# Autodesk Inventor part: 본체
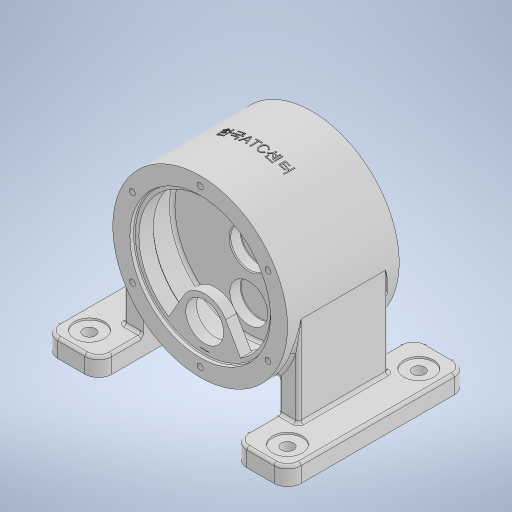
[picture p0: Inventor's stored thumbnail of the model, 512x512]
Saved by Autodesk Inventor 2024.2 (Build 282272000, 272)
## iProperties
Created: 2025-12
Part Number: 본체
Material: 일반
Document SubType Name: Modeling
Designer: home
Density: 1 g/cm^3
Appearance: 기본값
Author: home
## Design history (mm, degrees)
sketch "스케치1"
  geometry: L1 (135, -100)-(75, -100); L2 (75, -100)-(75, 100); L3 (75, 100)-(135, 100); L4 (135, 100)-(135, -100); L5 (-75, -100)-(-135, -100); L6 (-135, -100)-(-135, 100); L7 (-135, 100)-(-75, 100); L8 (-75, 100)-(-75, -100); 2 further points
  constraints: 16 end point, 4 parallel, 2 horizontal, 2 perpendicular, 1 midpoint
  dimensions: "d0" = 60 distance between parallel lines of L2 L4; "d1" = 60 distance between parallel lines of L6 L8; "d2" = 135 distance from line of point (0, 0) L4; "d3" = 135 distance from line of point (0, 0) L6; "d4" = 100 vertical distance of point (-105, -100) point (0, 0); "d5" = 100 distance from line of L7 point (0, 0); "d6" = 100 distance from line of point (0, 0) L1; "d7" = 100 distance from line of point (0, 0) L3
extrude "돌출1" new body sketch "스케치1" distance "d8" = 20; taper "d9" = 0 deg
sketch "스케치2"
  geometry: C1 r 97 at (0, 120); 1 further point
  constraints: 1 centre point, 1 vertical alignment
  dimensions: "d11" = 194 diameter of C1
extrude "돌출2" join sketch "스케치2" stored distance "d12" = 124; taper "d13" = 0 deg
sketch "스케치3"
  geometry: L1 (-135, 20)-(-75, 20) reference; L2 (75, 20)-(135, 20) reference; L3 (97, 120)-(97, 20); L4 (-97, 120)-(-97, 20); L5 (-75, 58.486)-(-75, 20); L6 (75, 20)-(75, 58.486); A1 r 97 centre (0, 120) between (97, 120) and (-97, 120) reference; 1 further point
  constraints: 8 end point, 4 point on circle, 2 perpendicular, 2 point on line, 2 tangent, 2 vertical
extrude "돌출3" join sketch "스케치3" stored distance "d14" = 100; taper "d15" = 0 deg
extrude "돌출4" join sketch "스케치3" stored distance "d16" = 100; taper "d17" = 0 deg
sketch "스케치4"
  geometry: L1 (120, 142.24)-(120, -159.656); L2 (0, 100)-(0, -100) reference; L3 (217, 62)-(23, 62) reference; L4 (23, -62)-(217, -62) reference; L5 (141, 8)-(141, -4); L6 (141, -4)-(120, -4); L7 (120, -4)-(120, 7.39); L8 (120, -4)-(139, -4); L9 (120, -13.476)-(120, -4); L10 (120, 62)-(198, 62); L11 (198, 62)-(198, 57); L12 (198, 57)-(120, 57); L13 (120, 57)-(120, 62); L14 (120, -62)-(198, -62); L15 (198, -62)-(198, -57); L16 (198, -57)-(120, -57); L17 (120, -57)-(120, -62); L18 (120, -57)-(193, -57); L19 (193, -57)-(193, -40); L20 (193, -40)-(120, -40); L21 (120, -40)-(120, -57); L22 (120, -40)-(205, -40); L23 (205, -40)-(205, -8); L24 (205, -8)-(120, -8); L25 (120, -8)-(120, -40); L26 (120, -4)-(139, -4); L27 (139, -4)-(139, -8); L28 (139, -8)-(120, -8); L29 (120, -8)-(120, -4); L30 (256.411, 0)-(-60.055, 0); L31 (205, 40)-(205, 8); L32 (205, 8)-(120, 8); L33 (120, 40)-(205, 40); L34 (141, 57)-(193, 57); L35 (193, 57)-(193, 40); L36 (193, 40)-(141, 40); L37 (141, 40)-(141, 57); L38 (67.5, 77.208)-(67.5, -163.094); L39 (120, 50)-(58.486, 50) reference; L40 (67.5, 57)-(88.5, 57); L41 (88.5, 57)-(88.5, 50); L42 (88.5, 50)-(67.5, 50); L43 (67.5, 50)-(67.5, 57); L44 (67.5, 50)-(89.75, 50); L45 (89.75, 50)-(89.75, 48.05); L46 (89.75, 48.05)-(67.5, 48.05); L47 (67.5, 48.05)-(67.5, 50); L48 (67.5, 48.05)-(88.5, 48.05); L49 (88.5, 48.05)-(88.5, 36.05); L50 (88.5, 36.05)-(67.5, 36.05); L51 (67.5, 36.05)-(67.5, 48.05); L52 (120, -4)-(67.5, -4); L53 (120, -8)-(67.5, -8); L54 (120, 8)-(67.5, 8); L55 (86.5, -4)-(86.5, -8); L56 (67.5, -4)-(88.5, -4); L57 (88.5, -4)-(88.5, 8); L58 (88.5, 8)-(67.5, 8); L59 (67.5, 8)-(67.5, -4); 23 further points
  constraints: 110 end point, 21 parallel, 13 perpendicular, 13 point on line, 12 horizontal, 4 symmetric about line, 2 midpoint, 2 vertical
  dimensions: "d18" = 120 distance between parallel lines of L2 L1; "d19" = 66 distance between parallel lines of L6 L3; "d20" = 42 diameter of L5 L1; "d22" = 5 distance of L10.end L11.end; "d23" = 156 diameter of L11 L1; "d24" = 5 distance of L14.end L15.end; "d25" = 156 diameter of L15 L1; "d26" = 22 distance between parallel lines of L4 L20; "d27" = 146 diameter of L19 L1; "d28" = 32 distance of L22.end L23.end; "d29" = 170 diameter of L23 L1; "d30" = 38 diameter of L27 L1; "d32" = 22 distance between parallel lines of L33 L3; "d35" = 146 diameter of L35 L1; "d37" = 42 diameter of L41 L38; "d38" = 44.5 diameter of L45 L38; "d39" = 1.95 distance between parallel lines of L46 L39; "d40" = 12 distance between parallel lines of L50 L46; "d41" = 42 diameter of L49 L38; "d42" = 19 distance of L6.end L8.end; "d43" = 42 diameter of L57 L38; "d44" = 38 diameter of L55 L38; "d47" = 52.5 distance between parallel lines of L38 L1
revolve "회전1" stored, may be unused: angle "d31" = 360 deg
revolve "회전2" stored, may be unused: angle "d45" = 90 deg
revolve "회전3" stored, may be unused: angle "d46" = 90 deg
fillet "모깎기1" dims "d48" = 15
sketch "스케치5"
  geometry: L1 (-135, 85)-(-135, -85) reference; L2 (-120, -100)-(-90, -100) reference; L3 (-75, -85)-(-75, -50) reference; L4 (-75, -50)-(-97, -50) reference; L5 (-97, -50)-(-97, 50) reference; L6 (-97, 50)-(-75, 50) reference; L7 (-75, 50)-(-75, 85) reference; L8 (-90, 100)-(-120, 100) reference; L9 (90, -100)-(120, -100) reference; L10 (135, -85)-(135, 85) reference; L11 (120, 100)-(90, 100) reference; L12 (75, 85)-(75, 50) reference; L13 (75, 50)-(97, 50) reference; L14 (97, 50)-(97, -50) reference; L15 (97, -50)-(75, -50) reference; L16 (75, -50)-(75, -85) reference; A1 r 15 centre (-120, 85) between (-120, 100) and (-135, 85) reference; A2 r 15 centre (-120, -85) between (-135, -85) and (-120, -100) reference; A3 r 15 centre (-90, -85) between (-90, -100) and (-75, -85) reference; A4 r 15 centre (-90, 85) between (-75, 85) and (-90, 100) reference; A5 r 15 centre (90, -85) between (75, -85) and (90, -100) reference; A6 r 15 centre (120, -85) between (120, -100) and (135, -85) reference; A7 r 15 centre (120, 85) between (135, 85) and (120, 100) reference; A8 r 15 centre (90, 85) between (90, 100) and (75, 85) reference; 1 further point
  node "투영된 루프1"
sketch "스케치6"
  geometry: L1 (0, -159.385)-(0, 176.547); L2 (184.988, 0)-(-326.881, 0); L3 (90, -100)-(120, -100) reference; L4 (135, -85)-(135, 85) reference; L5 (120, 100)-(90, 100) reference; L6 (75, 85)-(75, 50) reference; L7 (75, 50)-(97, 50) reference; L8 (97, 50)-(97, -50) reference; L9 (97, -50)-(75, -50) reference; L10 (75, -50)-(75, -85) reference; C1 r 16.5 at (110, -75); C2 r 16.5 at (110, 70.867); C3 r 16.5 at (-110, -75); C4 r 16.5 at (-110, 75); C5 r 6.75 at (110, -75); C6 r 6.75 at (110, 70.867); C7 r 6.75 at (-110, 75); C8 r 6.75 at (-110, -75); A1 r 15 centre (90, -85) between (75, -85) and (90, -100) reference; A2 r 15 centre (120, -85) between (120, -100) and (135, -85) reference; A3 r 15 centre (120, 85) between (135, 85) and (120, 100) reference; A4 r 15 centre (90, 85) between (90, 100) and (75, 85) reference; 1 further point
  constraints: 8 centre point, 4 coincident, 4 end point, 1 horizontal, 1 vertical
  dimensions: "d49" = 33 diameter of C1; "d50" = 33 diameter of C2; "d51" = 33 diameter of C3; "d52" = 33 diameter of C4; "d53" = 110 distance from line of L1 C2.centre; "d54" = 110 distance from line of L1 C4.centre; "d55" = 75 distance from line of L2 C4.centre; "d56" = 75 distance from line of L2 C3.centre; "d57" = 75 distance from line of L2 C1.centre; "d58" = 110 distance from line of L1 C1.centre; "d59" = 110 distance from line of C3.centre L1; "d62" = 13.5 diameter of C5; "d63" = 13.5 diameter of C6; "d64" = 13.5 diameter of C7; "d65" = 13.5 diameter of C8
  node "투영된 루프2"
extrude "돌출5" cut sketch "스케치6" distance "d60" = 2; taper "d61" = 0 deg
extrude "돌출6" cut sketch "스케치6" extent not by distance; stored distance "d66" = 0; taper "d67" = 0 deg
node "작업 평면3"
sketch "스케치7"
  geometry: L1 (-148.801, -5.955)-(165.111, -5.955); L2 (-23.383, -32.455)-(-43.991, -68.149); L3 (23.383, -32.455)-(39.928, -61.112); L4 (0, -120)-(0, 226.545); C1 r 21 at (0, -45.955); A1 r 22.25 centre (0, -52.5) between (-10.174, -72.287) and (10.174, -72.287) reference; A2 r 27 centre (0, -45.955) between (-23.383, -32.455) and (23.383, -32.455); A3 r 73 centre (0, 0) between (-10.174, -72.287) and (10.174, -72.287) reference; A4 r 73 centre (0, 0) between (5.368, -72.802) and (-5.368, -72.802) reference; 1 further point
  constraints: 8 end point, 3 point on circle, 2 centre point, 2 tangent, 1 coincident, 1 horizontal, 1 vertical, 1 vertical alignment
  dimensions: "d70" = 54 diameter of A2; "d71" = 40 distance from line of L1 A2.centre; "d72" = 4.02262 distance from line of A4.centre L3; "d73" = 30 deg angle of L3 L4; "d74" = 30 deg angle of L4 L2; "d75" = 42 diameter of C1
extrude "돌출7" join sketch "스케치7" stored distance "d76" = 12; taper "d77" = 0 deg
sketch "스케치9"
  geometry: L1 (0, 0)-(125.513, 72.465); L2 (0, 0)-(0, 156.228); L3 (0, 0)-(200.697, -115.873); L4 (0, 0)-(0, -237.75); L5 (0, 0)-(-224.304, 129.502); L6 (0, 0)-(-206.493, -119.219); C1 r 97 at (0, 0) reference; C2 r 78 at (0, 0) reference; C3 r 21 at (0, 0) reference; A1 r 87 centre (0, 0) between (0, 87) and (75.344, 43.5); 5 further points
  constraints: 12 end point, 6 point on circle, 5 point on line, 1 centre point, 1 coincident, 1 vertical
  dimensions: "d86" = 174 diameter of A1; "d94" = 60 deg angle of L1 L2; "d95" = 60 deg angle of L5 L2; "d96" = 60 deg angle of L3 L1; "d97" = 60 deg angle of L3 L4; "d98" = 60 deg angle of L6 L4
hole "구멍2" sketch "스케치9" diameter "d87" = 6.647; stored, may be unused: countersink angle "d91" = 90 deg, drill point angle "d93" = 118 deg; dims "d88" = 16, "d89" = 4, "d90" = 2, "d92" = 18
hole "구멍3" sketch "스케치9" diameter "d99" = 6.647; stored, may be unused: countersink angle "d103" = 90 deg, drill point angle "d105" = 118 deg; dims "d100" = 16, "d101" = 4, "d102" = 2, "d104" = 18
fillet "모깎기2" dims "d106" = 3
fillet "모깎기4" dims "d108" = 3
chamfer "모따기1" distance "d109" = 1; stored, may be unused: second distance "d110" = 2, angle "d111" = 45 deg
sketch "스케치10"
  geometry: L1 (-75, 22.196)-(-75, 58.486) reference; L2 (-75, 0)-(-75, 17) reference; L3 (-75, 17)-(-75, 22.196) reference; L4 (75, 58.486)-(75, 17) reference; L5 (75, 17)-(75, 0) reference; L6 (0, 120.325)-(0, -118.414); L7 (-75, 8)-(-36.6, 30.17); L8 (-75, 0)-(-90, 0) reference; L9 (75, 8)-(36.6, 30.17); L10 (-78, 23)-(-94, 23) reference; L11 (-75, 22.196)-(-75, 58.486) reference; L12 (-94, 23)-(-94, 96.063) reference; C1 r 3.324 at (75.344, 76.5) reference; C2 r 3.324 at (0, 33) reference; C3 r 3.324 at (-75.344, 76.5) reference; C4 r 3.324 at (-75.344, 163.5) reference; C5 r 3.324 at (75.344, 163.5) reference; C6 r 3.324 at (0, 207) reference; C7 r 78 at (0, 120) reference; C8 r 97 at (0, 120) reference; C9 r 97 at (0, 120) reference; C10 r 97 at (0, 120) reference; C11 r 78 at (0, 120) reference; A1 r 6 centre (-78, 17) between (-75, 22.196) and (-78, 23) reference; A2 r 97 centre (0, 120) between (-94, 96.063) and (-75, 58.486) reference; A3 r 97 centre (0, 120) between (-94, 96.063) and (-78, 62.337) reference; A4 r 97 centre (0, 120) between (-94, 96.063) and (-75, 58.486) reference; A5 r 97 centre (0, 120) between (78, 62.337) and (94, 96.063) reference; A6 r 97 centre (0, 120) between (78, 62.337) and (94, 96.063) reference; 15 further points
  constraints: 6 end point, 2 symmetric about line, 2 vertical, 1 point on line, 12 other
  dimensions: "d112" = 8 distance from line of L8 L7.start; "d113" = 60 deg angle of L7 L1
  node "투영된 루프3"
  node "투영된 루프4"
  node "투영된 루프5"
extrude "돌출8" join sketch "스케치10" stored distance "d114" = 12; taper "d115" = 0 deg
extrude "돌출9" join sketch "스케치10" stored distance "d116" = 12; taper "d117" = 0 deg
fillet "모깎기5" dims "d118" = 3
fillet "모깎기6" dims "d119" = 3
sketch "스케치13"
  geometry: 1 further point
node "작업 평면4"
fillet "모깎기7" dims "d120" = 3
fillet "모깎기8" dims "d121" = 0.6
chamfer "모따기2" distance "d122" = 1; stored, may be unused: second distance "d123" = 2, angle "d124" = 45 deg
sketch "스케치14"
  geometry: 2 further points
  constraints: 1 other
feature "엠보싱1" sketch "스케치14" dims "d125" = 0.5, "d126" = 0
node "솔리드1"
mirror "미러1"
feature "A9D066F2-1C7D-4E18-AEED-F7BC21143FA4" dims "d87" = 6.647, "d88" = 16, "d89" = 4, "d90" = 2, "d91" = 90 deg, "d92" = 18, "d93" = 118 deg
other parameters: "d68" = -11
